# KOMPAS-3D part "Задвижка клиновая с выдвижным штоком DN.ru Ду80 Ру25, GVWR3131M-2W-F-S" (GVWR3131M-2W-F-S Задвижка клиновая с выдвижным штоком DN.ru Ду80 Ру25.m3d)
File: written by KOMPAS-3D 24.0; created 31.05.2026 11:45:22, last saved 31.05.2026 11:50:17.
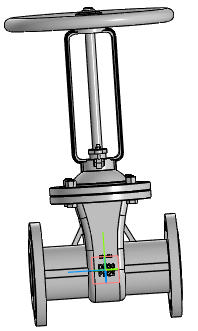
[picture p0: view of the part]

Document properties: Автор: R2D2; Полное имя файла: E:\Работа\Зайцев\GVWR3131M-2W-F-S Задвижка клиновая 30нж64нж DN.ru  Ду50-150 Ру25\исходные данные\DN80\GVWR3131M-2W-F-S Задвижка клиновая с выдвижным штоком DN.ru Ду80 Ру25.m3d

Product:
- Component [detail]: Деталь2  | qty 1  | pos. 1  | Автор: R2D2; additional columns: Типовые; source file: Деталь2 Деталь2.m3d
- Component [detail]: AS 1110 - M12 x 45  | qty 4  | pos. 2  | Комментарий: Болты и винты   шестигранные точные   метрические ISO; Автор: R2D2; additional columns: Сталь, мягкая; source file: AS 1110 - M12 x 45 AS 1110 - M12 x 45.m3d
- Component [detail]: ANSI B18.2.4.2M - M12x1,75 - 18  | designation ANSI B18.2.4.2M - M12x1,75  | qty 4  | pos. 3  | Комментарий: Типы метрических   шестигранных гаек   2; Автор: R2D2; additional columns: Сталь, мягкая; source file: ANSI B18.2.4.2M - M12x1,75 ANSI B18.2.4.2M - M12x1,75 - 18.m3d
- Component [detail]: ANSI B18.2.4.2M - M5x0,8 - 8  | designation ANSI B18.2.4.2M - M5x0,8  | qty 2  | pos. 4  | Комментарий: Типы метрических   шестигранных гаек   2; Автор: R2D2; additional columns: Сталь, мягкая; source file: ANSI B18.2.4.2M - M5x0,8 ANSI B18.2.4.2M - M5x0,8 - 8.m3d
- Component [detail]: Деталь1  | qty 1  | pos. 5  | additional columns: Типовые; source file: 2.m3d
- Component [detail]: Деталь1  | qty 1  | pos. 5  | Автор: R2D2; additional columns: Типовые; source file: 3.m3d
- Component [detail]: Деталь1  | qty 2  | pos. 5  | Автор: R2D2; additional columns: Типовые; source file: 1.m3d
- Part/product: Задвижка клиновая с выдвижным штоком DN.ru Ду80 Ру25  | designation GVWR3131M-2W-F-S
    Масса: 25.5
    Раздел спецификации: Прочие изделия
    Примечание: D040-09368

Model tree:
1. Массив по концентрической сетке:1  (labels: Грань.Твердое тело1)  (4 pattern instances)
     Шаг 2 = 360
2. Массив по концентрической сетке:2  (labels: Грань.Твердое тело1)  (2 pattern instances)
     Шаг 2 = 360
3. Элемент выдавливания:1  (with: Грань.Элемент выдавливания:2, Грань.Элемент выдавливания:1)
     Расстояние 1 = 125.25
4. Элемент выдавливания:2  (with: Грань.Элемент выдавливания:1, Грань.Элемент вращения:1)
     Расстояние 1 = 42.7058
5. Элемент выдавливания:3  (with: Грань.Элемент выдавливания:1, Грань.Элемент вращения:1)
     Расстояние 1 = 37.7507
6. Эскиз:1
7. Элемент выдавливания:4  (with: Грань.Элемент выдавливания:1, Грань.Элемент вращения:1)  (labels: Грань.Твердое тело1; Грань.Solid1; Твердое тело1)
     Расстояние 1 = 61; Смещение 1 = 1; Расстояние = -495; Расстояние = -140; Ориентация = 2

Referenced files in E:\Работа\Зайцев\GVWR3131M-2W-F-S Задвижка клиновая 30нж64нж DN.ru  Ду50-150 Ру25\исходные данные\DN80\: Деталь2 Деталь2.m3d, AS 1110 - M12 x 45 AS 1110 - M12 x 45.m3d, ANSI B18.2.4.2M - M12x1,75 ANSI B18.2.4.2M - M12x1,75 - 18.m3d, ANSI B18.2.4.2M - M5x0,8 ANSI B18.2.4.2M - M5x0,8 - 8.m3d, 2.m3d, 3.m3d, 1.m3d
Referenced files in E:\Работа\Зайцев\GVWR3131M-2W-F-S Задвижка клиновая с выдвижным штоком DN.ru Ду50-200 Ру63\DN80\исходные материалы\: 1.m3d, ANSI B18.2.4.2M - M12x1,75 ANSI B18.2.4.2M - M12x1,75 - 18.m3d, AS 1110 - M12 x 45 AS 1110 - M12 x 45.m3d, ANSI B18.2.4.2M - M5x0,8 ANSI B18.2.4.2M - M5x0,8 - 8.m3d
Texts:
  GVWR3131M-2W-F-S
  DN80
  GOST 26.020 Pr3
  PN25
  Деталь2 Деталь2
  AS 1110 - M12 x 45 AS 1110 - M12 x 45 (1)
  ANSI B18.2.4.2M - M12x1,75 ANSI B18.2.4.2M - M12x1,75 - 18 (1)
  ANSI B18.2.4.2M - M5x0,8 ANSI B18.2.4.2M - M5x0,8 - 8 (1)
  Деталь1 Деталь1
  Деталь1 Деталь1 (1)
  Деталь1 Деталь1 (2)
  Ось Y.Начало координат
  Ось Z.Начало координат
  Плоскость ZX.Начало координат
  Плоскость XY.Начало координат
  Solid1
